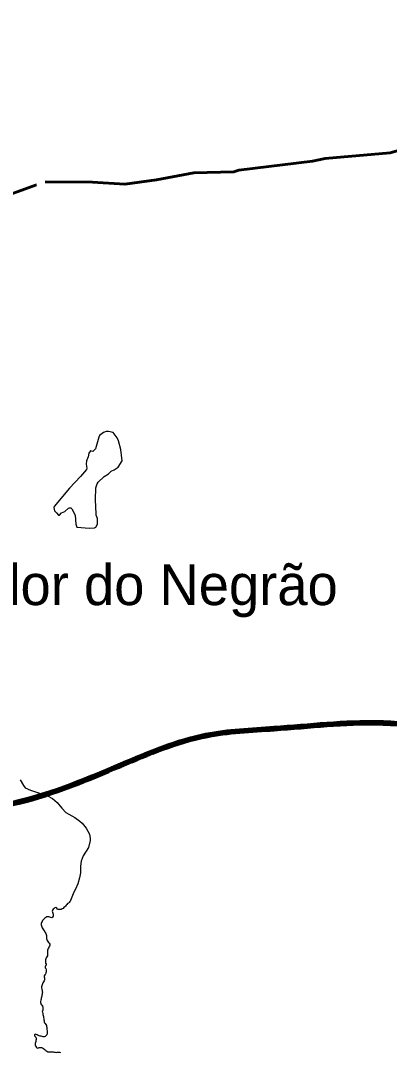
# Model space of a CAD drawing. Extents: x -1643653 to 4543381, y 1624270 to 13878484.
# Drawn here: x 733703 to 738239, y 8963412 to 8976106 of the extents above; entities that cross this region are included whole.
import ezdxf

# ---------------------------------------------------------------- set-up
doc = ezdxf.new("R2010")
doc.units = 0
doc.header["$LTSCALE"] = 200
doc.linetypes.add('LONG_DASH_SHORT_DASH', pattern=[9.9, 6, -1.2, 1.5, -1.2])
for name, color, linetype, lineweight in [('21', 7, 'Continuous', 25), ('24', 7, 'Continuous', 25), ('26', 7, 'Continuous', 106), ('28', 7, 'Continuous', 53), ('60', 7, 'Continuous', 13), ('7', 7, 'LONG_DASH_SHORT_DASH', 60)]:
    doc.layers.add(name, color=color, linetype=linetype, lineweight=lineweight)
doc.layers.add('41', color=7, linetype='Continuous')

msp = doc.modelspace()

# ---------------------------------------------------------------- linework, layer by layer
at = {"layer": '21'}
for points in [[(734441.2, 8970498.9), (734303.8, 8970355.7), (734116.5, 8970129.9), (734113.1, 8970114.7), (734119.4, 8970075.5), (734145.2, 8970051.2), (734168.9, 8970019.5), (734181.4, 8970021.5), (734206.5, 8970050.8), (734247.2, 8970065.8), (734290.4, 8970107.4), (734303.5, 8970111.7), (734321.8, 8970111.1), (734333.6, 8970097.9), (734375, 8970020.5), (734381.7, 8969909.7), (734389.7, 8969884.2), (734396.2, 8969874.8), (734551.2, 8969860.5), (734613.7, 8969866.7), (734627.4, 8969872.6), (734648.3, 8969912.4), (734649.6, 8969980.8), (734634.3, 8970019.7), (734630.8, 8970039.7), (734623.8, 8970209), (734629.4, 8970357.2), (734643.8, 8970405.7), (734658.9, 8970427.2), (734730.6, 8970496.3), (734782.1, 8970530.8), (734817.5, 8970561.3), (734855.2, 8970579.8), (734904.2, 8970611.7), (734951.1, 8970691.3), (734935.8, 8970827.7), (734908.4, 8970936.3), (734891.3, 8970974.5), (734841.3, 8971037.1), (734782.7, 8971051.2)], [(734782.7, 8971051.2), (734756.2, 8971050.8), (734720.8, 8971040.1), (734672, 8971001.4), (734663.3, 8970981.6), (734624.9, 8970837.4), (734592.1, 8970806.3), (734562.4, 8970812), (734543.6, 8970783.7), (734532, 8970740.5), (734512.6, 8970689.2), (734508.8, 8970650.1), (734519.5, 8970599.8), (734514.8, 8970584.3), (734441.2, 8970498.9)]]:
    msp.add_lwpolyline(points, dxfattribs=at)
at = {"layer": '24'}
for points in [[(733697.2, 8966763.3), (733739, 8966694.9), (733760.7, 8966668.4), (733825.8, 8966637.8), (733959, 8966591.6), (734034.5, 8966569.7), (734094.6, 8966536.2), (734151.5, 8966485), (734209.2, 8966415.7), (734259.6, 8966363.7), (734370.9, 8966301.9), (734433.4, 8966256), (734458.6, 8966232.5), (734511.2, 8966171.1), (734552, 8966096.3), (734560.3, 8966041.1), (734559.6, 8966020.2), (734537.3, 8965930.7), (734471.1, 8965828), (734446.2, 8965764.4), (734439.5, 8965701), (734438, 8965620.3), (734427.4, 8965560.6), (734408.2, 8965484.4), (734379, 8965420.6), (734356.7, 8965384.2), (734317.4, 8965278.9)], [(734317.4, 8965278.9), (734316.7, 8965277.6), (734309.6, 8965266), (734300.3, 8965256.2), (734290.8, 8965248), (734280, 8965241.5), (734271, 8965232.4), (734262.1, 8965222.2), (734255.2, 8965210.8), (734246, 8965201.4), (734235.3, 8965192.4), (734225.2, 8965183.6), (734214.5, 8965176.8), (734203.3, 8965171.2), (734191.1, 8965169), (734176.5, 8965168.2), (734165.4, 8965170.5), (734153.3, 8965175.2), (734146.5, 8965187.1), (734135.5, 8965193.7), (734123.7, 8965189.1), (734113.9, 8965181), (734104.7, 8965171.5), (734096.9, 8965160.2), (734092, 8965148.5), (734093.8, 8965135.7), (734099.1, 8965124.2), (734101.8, 8965111.2), (734104.4, 8965098.9), (734101.7, 8965086.3), (734094.8, 8965075.1), (734085.3, 8965066.8), (734072.7, 8965069.6), (734061.6, 8965075.9), (734048.7, 8965077.6), (734035.9, 8965079.3), (734022.6, 8965077.8), (734012.9, 8965069.3), (734002.3, 8965061.6), (733992.1, 8965054.2), (733982.6, 8965044.5), (733973.5, 8965035.4), (733966.4, 8965023.8), (733961.2, 8965011.2), (733957.4, 8964996.8), (733956.8, 8964980.1), (733961.7, 8964967.6), (733965, 8964954.8), (733969.4, 8964942.7), (733975.5, 8964931.1), (733983, 8964920.4), (733992.3, 8964907.2), (733999.9, 8964896), (734007, 8964885.5), (734014.1, 8964874.7), (734019.1, 8964863.1), (734023, 8964850.6), (734021.8, 8964836.9), (734020.6, 8964824.1), (734020.5, 8964810.9), (734024.2, 8964798.7), (734031.2, 8964786.5), (734039.1, 8964776.3), (734045.8, 8964764.7), (734054.2, 8964754.9)], [(734054.2, 8964754.9), (734060.9, 8964743.3), (734062.1, 8964730.9), (734057.1, 8964716.4), (734051.1, 8964704.2), (734044.2, 8964692), (734039, 8964679.5), (734033.5, 8964667.7), (734031.7, 8964654.4), (734034.2, 8964641.1), (734034.2, 8964628.3), (734034.1, 8964613), (734031.7, 8964599), (734024.3, 8964586.6), (734018.8, 8964574.7), (734012.7, 8964563), (734010, 8964550.6), (734009.5, 8964537.9), (734009, 8964524.6), (734010.7, 8964510.9), (734016.3, 8964498.6), (734016.6, 8964486), (734010.2, 8964474.6), (734005, 8964463.3), (734003.8, 8964450.7), (734012.6, 8964441.7), (734016, 8964428.6), (734016.2, 8964415.1), (734015.3, 8964401.5), (734012.5, 8964389.2), (734008.2, 8964375), (733999.7, 8964365), (733992.6, 8964354.2), (733992.8, 8964341.2), (733995.2, 8964328.2), (733996.5, 8964315.3), (733996.1, 8964302.6)], [(733996.1, 8964302.6), (733991.3, 8964290.8), (733985.7, 8964278.4), (733977, 8964266.7), (733970.8, 8964254.3), (733966.8, 8964241.9), (733962.8, 8964229.6), (733960.8, 8964216.6), (733959.5, 8964204), (733963.7, 8964190.5), (733968, 8964177.9), (733970, 8964165.6), (733970.8, 8964152.7), (733969.3, 8964140.3), (733967.8, 8964127), (733965.9, 8964114.5), (733963.3, 8964101.8), (733960.2, 8964089.4), (733957.5, 8964076.7), (733954, 8964064.3), (733950.2, 8964052), (733949.4, 8964039.4), (733948.8, 8964026.1), (733950.4, 8964013.4), (733956.9, 8964002.4), (733964.9, 8963992.1), (733970.9, 8963980.8), (733975.1, 8963967.2), (733977.1, 8963954.1), (733977.3, 8963941.3), (733974.7, 8963928.5), (733969.8, 8963916.5), (733973.1, 8963904.2), (733975.6, 8963891), (733978.1, 8963878), (733980.9, 8963864.1), (733983.6, 8963851.7), (733985.7, 8963839), (733987.3, 8963825.2), (733990.2, 8963813), (733991.4, 8963800.2), (733993.4, 8963787.4), (733998.3, 8963775.9), (734004.5, 8963764.8), (734011.8, 8963753.8), (734019.7, 8963743.9), (734023.1, 8963731.8), (734024.4, 8963719), (734025.3, 8963704.3), (734026.4, 8963691.4), (734027.8, 8963677.9), (734028.3, 8963664.8), (734028.3, 8963651.9), (734028.2, 8963639.3), (734025.8, 8963627), (734017.3, 8963617.8), (734005.2, 8963608.5), (733993.3, 8963604.6), (733979.8, 8963604.3), (733967.2, 8963605.8), (733955.4, 8963610.6), (733942.5, 8963609.8), (733929.6, 8963614), (733918.5, 8963620.1), (733907.4, 8963627.1)], [(733907.4, 8963627.1), (733896, 8963632.6), (733883.9, 8963636.4), (733873.5, 8963629), (733873.4, 8963616.1), (733881.9, 8963606.8), (733890.4, 8963597.1), (733892.8, 8963584.5), (733892.8, 8963571.2), (733891.7, 8963557.6), (733888.4, 8963545.2), (733885.2, 8963532.5), (733883.4, 8963519.3), (733883.6, 8963506.2), (733884.6, 8963493.5), (733889.7, 8963481.7), (733897.6, 8963469.9), (733908.2, 8963462.6), (733921.2, 8963465.7), (733932.8, 8963471.8), (733947.2, 8963473.3), (733959.5, 8963471.2), (733971.9, 8963465.6), (733982.9, 8963458.6), (733993.4, 8963451), (734003.9, 8963442.6), (734014.3, 8963435.6), (734024.7, 8963427.4), (734036.2, 8963420), (734048.7, 8963417.4), (734061.5, 8963417), (734075.2, 8963416.7), (734088.5, 8963416.8), (734101.5, 8963418.1), (734115.2, 8963415.3), (734127.4, 8963412.7), (734140.3, 8963411.9)], [(734140.3, 8963411.9), (734153.1, 8963412.5), (734166.7, 8963413), (734179.8, 8963413), (734192.9, 8963411.4)]]:
    msp.add_lwpolyline(points, dxfattribs=at)
at = {"layer": '26'}
msp.add_spline([(738852.4, 8967397.8), (738119.2, 8967456.1), (736819.8, 8967385.2), (735978.7, 8967299.6), (734932.4, 8966935.1), (733681.7, 8966482.5), (732152.4, 8966285.3), (730470.8, 8966190.5), (727806.8, 8965794.5), (726426, 8965189.7), (726351.8, 8965240.9), (726326.3, 8965228.3)], degree=3, dxfattribs=at)
at = {"layer": '28'}
msp.add_spline([(738852.4, 8967424), (738119.2, 8967482.3), (736819.8, 8967411.3), (735978.7, 8967325.8), (734932.4, 8966961.3), (733681.7, 8966508.6), (732152.4, 8966311.4), (730470.8, 8966216.6), (727806.8, 8965820.6), (726426, 8965215.8), (726351.8, 8965267.1), (726326.3, 8965254.5)], degree=3, dxfattribs=at)
at = {"layer": '60', "lineweight": 25}
msp.add_spline([(814781, 9009175.5), (814787.2, 9009173.4), (814796.9, 9009173.4), (814799.4, 9009172.4), (814805.1, 9009174.5), (814805.6, 9009176.5), (814811.7, 9009179.5), (814811.7, 9009179.5), (814801.5, 9009181), (814790.7, 9009181.5), (814784.1, 9009183.1), (814777.4, 9009185.1), (814778.4, 9009175.5)], degree=3, dxfattribs=at)
at = {"layer": '7'}
msp.add_lwpolyline([(732767.6, 8973679.2), (734004.4, 8974123.6), (734587.5, 8974117.1), (734986.3, 8974093.8), (735372.7, 8974147.2), (735835.4, 8974235.1), (736327.4, 8974244.9), (736385.3, 8974265.2), (737292.2, 8974376.7), (737450.9, 8974411), (738250.7, 8974481.5), (738334.6, 8974505.4), (740923.3, 8974839.9), (743944.6, 8975116), (743973.3, 8975101.7), (744524.3, 8975159.5), (745697.7, 8975189)], dxfattribs=at)

# ---------------------------------------------------------------- texts
at = {"layer": '41'}
msp.add_text('Minador do Negrão', height=500, dxfattribs=at).set_placement((731880.7, 8968914.6))

doc.saveas('drawing.dxf')
